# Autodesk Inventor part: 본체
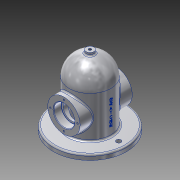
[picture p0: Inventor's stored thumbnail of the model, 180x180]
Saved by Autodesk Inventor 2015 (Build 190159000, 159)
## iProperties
Created: 2019-11
Part Number: 본체
Material: 알루미늄 6061
Document SubType Name: Modeling
Designer: 1010101
Density: 2.7 g/cm^3
Appearance: 알루미늄 - 평지
Author: 1010101
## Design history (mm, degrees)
sketch "스케치1"
  geometry: C1 r 70 at (0, 0); 1 further point
  constraints: 1 centre point, 1 coincident
  dimensions: "d0" = 140 diameter of C1
extrude "돌출1" new body sketch "스케치1" distance "d1" = 10; taper "d2" = 0 deg
sketch "스케치2"
  geometry: C1 r 70 at (0, 0) reference; C2 r 40 at (0, 0)
  constraints: 1 centre point, 1 coincident
  dimensions: "d3" = 80 diameter of C2
extrude "돌출2" join sketch "스케치2" distance "d4" = 80; taper "d5" = 0 deg
sketch "스케치4"
  geometry: L1 (70, 10)-(70, 0) reference; L2 (70, 0)-(-70, 0) reference; L3 (-70, 0)-(-70, 10) reference; L4 (-70, 10)-(-40, 10) reference; L5 (-40, 10)-(-40, 90) reference; L6 (-40, 90)-(40, 90) reference; L7 (40, 90)-(40, 10) reference; L8 (40, 10)-(70, 10) reference; A1 r 40 centre (0, 90) between (40, 90) and (-40, 90); 1 further point
  constraints: 2 end point, 2 point on circle, 1 centre point, 1 midpoint
revolve "회전1" sketch "스케치4" stored, may be unused: angle "d8" = 90 deg
node "작업 평면1"
sketch "스케치5"
  geometry: L1 (-70, 0)-(70, 0) reference; C1 r 31 at (0, 50); 2 further points
  constraints: 1 centre point, 1 coincident, 1 vertical alignment
  dimensions: "d10" = 50 distance from line of point (0, 50) L1; "d11" = 62 diameter of C1
extrude "돌출3" join sketch "스케치5" stored distance "d12" = 80; taper "d13" = 0 deg
sketch "스케치6"
  geometry: C1 r 31 at (0, 0) reference; C2 r 20 at (0, 0); 1 further point
  constraints: 1 centre point, 1 coincident
  dimensions: "d14" = 40 diameter of C2
extrude "돌출4" cut sketch "스케치6" distance "d15" = 15; taper "d16" = 0 deg
sketch "스케치7"
  geometry: C1 r 20 at (0, 0) reference; C2 r 16.5 at (0, 0); 1 further point
  constraints: 1 centre point, 1 coincident
  dimensions: "d17" = 33 diameter of C2
extrude "돌출5" cut sketch "스케치7" distance "d18" = 35; taper "d19" = 0 deg
sketch "스케치8"
  geometry: C1 r 20 at (0, 0) reference; 2 further points
  constraints: 1 vertical alignment
  dimensions: "d20" = 26 distance of C1.centre point (0, 26)
hole "구멍1" sketch "스케치8" at (0, 26) diameter "d21" = 3.242; stored, may be unused: countersink angle "d25" = 90 deg, drill point angle "d27" = 118 deg; dims "d22" = 8, "d23" = 4, "d24" = 2, "d26" = 10
sketch "스케치9"
  geometry: C1 r 70 at (0, 0) reference; C2 r 30 at (0, 0)
  constraints: 1 centre point, 1 coincident
  dimensions: "d31" = 60 diameter of C2
extrude "돌출6" cut sketch "스케치9" distance "d32" = 90; taper "d33" = 0 deg
sketch "스케치10"
  geometry: L1 (-50, 81)-(-40, 81) reference; L2 (-40, 81)-(-40, 90) reference; L3 (40, 90)-(40, 81) reference; L4 (40, 81)-(50, 81) reference; L5 (50, 81)-(50, 77.621) reference; L6 (50, 77.621)-(40, 77.621) reference; L7 (40, 77.621)-(39.026, 76) reference; L8 (39.026, 76)-(40, 74.379) reference; L9 (40, 74.379)-(50, 74.379) reference; L10 (50, 74.379)-(50, 70) reference; L11 (50, 70)-(35, 70) reference; L12 (35, 70)-(35, 66.5) reference; L13 (35, 66.5)-(30, 66.5) reference; L14 (30, 66.5)-(30, 90) reference; L15 (30, 90)-(-30, 90) reference; L16 (-30, 90)-(-30, 66.5) reference; L17 (-30, 66.5)-(-35, 66.5) reference; L18 (-35, 66.5)-(-35, 70) reference; L19 (-35, 70)-(-50, 70) reference; L20 (-50, 70)-(-50, 74.379) reference; L21 (-50, 74.379)-(-40, 74.379) reference; L22 (-40, 74.379)-(-39.026, 76) reference; L23 (-39.026, 76)-(-40, 77.621) reference; L24 (-40, 77.621)-(-50, 77.621) reference; L25 (-50, 77.621)-(-50, 81) reference; L26 (-70, 0)-(-70, 10) reference; L27 (-70, 10)-(-40, 10) reference; L28 (-40, 10)-(-40, 19) reference; L29 (-40, 19)-(-50, 19) reference; L30 (-50, 19)-(-50, 22.379) reference; L31 (-50, 22.379)-(-40, 22.379) reference; L32 (-40, 22.379)-(-39.026, 24) reference; L33 (-39.026, 24)-(-40, 25.621) reference; L34 (-40, 25.621)-(-50, 25.621) reference; L35 (-50, 25.621)-(-50, 30) reference; L36 (-50, 30)-(-35, 30) reference; L37 (-35, 30)-(-35, 33.5) reference; L38 (-35, 33.5)-(-30, 33.5) reference; L39 (-30, 33.5)-(-30, 0) reference; L40 (-30, 0)-(-70, 0) reference; L41 (70, 10)-(70, 0) reference; L42 (70, 0)-(30, 0) reference; L43 (30, 0)-(30, 33.5) reference; L44 (30, 33.5)-(35, 33.5) reference; L45 (35, 33.5)-(35, 30) reference; L46 (35, 30)-(50, 30) reference; L47 (50, 30)-(50, 25.621) reference; L48 (50, 25.621)-(40, 25.621) reference; L49 (40, 25.621)-(39.026, 24) reference; L50 (39.026, 24)-(40, 22.379) reference; L51 (40, 22.379)-(50, 22.379) reference; L52 (50, 22.379)-(50, 19) reference; L53 (50, 19)-(40, 19) reference; L54 (40, 19)-(40, 10) reference; L55 (40, 10)-(70, 10) reference; A1 r 40 centre (0, 90) between (40, 90) and (-40, 90) reference; A2 r 30 centre (0, 90) between (30, 90) and (-30, 90); 1 further point
  constraints: 2 end point, 2 point on circle, 1 centre point, 1 coincident
revolve "회전2" sketch "스케치10" stored, may be unused: angle "d35" = 90 deg
fillet "모깎기1" dims "d36" = 0.3
chamfer "모따기1" distance "d37" = 1; stored, may be unused: second distance "d38" = 2, angle "d39" = 45 deg
fillet "모깎기2" dims "d40" = 3
fillet "모깎기3" dims "d41" = 3
node "작업 평면2"
sketch "스케치11"
  geometry: C1 r 7.5 at (0, 0); 1 further point
  constraints: 1 centre point, 1 coincident
  dimensions: "d43" = 15 diameter of C1
extrude "돌출7" join sketch "스케치11" stored distance "d44" = 15 (= d43); taper "d45" = 0 deg
fillet "모깎기4" dims "d46" = 3
sketch "스케치12"
  geometry: C1 r 7.5 at (0, 0) reference
hole "구멍2" sketch "스케치12" at (0, 0) diameter "d47" = 5.188; stored, may be unused: countersink angle "d51" = 90 deg, drill point angle "d53" = 118 deg; dims "d48" = 12, "d49" = 4, "d50" = 2, "d52" = 40
node "작업 평면3"
sketch "스케치13"
  geometry: L1 (30, 0)-(-30, 0) reference; 2 further points
  constraints: 1 vertical alignment, 1 other
  dimensions: "d55" = 50 distance from line of L1 point (0, 50)
feature "엠보싱1" sketch "스케치13" dims "d10" = 50, "d11" = 62, "d56" = 0.5, "d57" = 0
sketch "스케치15"
  geometry: C1 r 30 at (0, 0) reference; 2 further points
  constraints: 2 horizontal alignment
  dimensions: "d61" = 55 distance of C1.centre point (-55, 0); "d62" = 55 distance of C1.centre point (55, 0)
hole "구멍3" sketch "스케치15" at (-55, 0), (55, 0) diameter "d63" = 9; stored, may be unused: countersink angle "d67" = 90 deg, drill point angle "d69" = 0 deg; dims "d64" = 12, "d65" = 4, "d66" = 2, "d68" = 40
node "솔리드1"
pattern_circular "원형 패턴1" dims angle "d29" = 360 deg
mirror "대칭2"
node "절단 모서리 투영1"
node "절단 모서리 투영2"
other parameters: "d42" = 135
